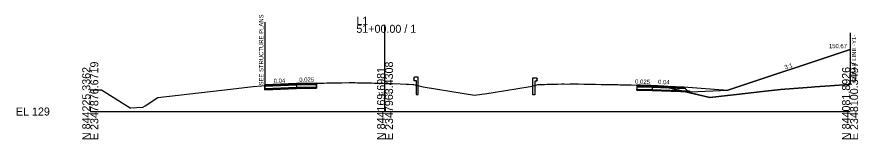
# Model space of a CAD drawing. Extents: x -26 to 2348258, y -10 to 844496.
# Drawn here: x 1322.4 to 1616.7, y 1990.3 to 2033.2 of the extents above; entities that cross this region are included whole.
import ezdxf

# ---------------------------------------------------------------- set-up
doc = ezdxf.new("R2010")
doc.units = 0
for name, color, linetype in [('Exist Cross Section Cell', 7, 'Continuous'), ('Exist XS Center Line Elevation Label', 7, 'Continuous'), ('Exist XS Ground Line', 7, 'Continuous'), ('Prop CMT Guardrail Graphics', 7, 'Continuous'), ('Prop CMT Pvmt Course 1', 7, 'Continuous'), ('Prop CMT Pvmt Course 2', 7, 'Continuous'), ('Prop CMT Pvmt Course 3', 7, 'Continuous'), ('Prop CMT Pvmt Course 4', 7, 'Continuous'), ('Prop CMT Pvmt Surface', 7, 'Continuous'), ('Prop CMT Shld Paved Course 1', 7, 'Continuous'), ('Prop CMT Shld Paved Course 2', 7, 'Continuous'), ('Prop CMT Shld Paved Course 3', 7, 'Continuous'), ('Prop CMT Shld Paved Course 4', 7, 'Continuous'), ('Prop CMT Slope Grass', 7, 'Continuous'), ('Prop CMT Subgrade Earthwork', 7, 'Continuous'), ('Prop XS Earthwork Shape', 7, 'Continuous'), ('Prop XS SE Text', 7, 'Continuous'), ('Prop XS Shear Point Element', 7, 'Continuous'), ('Prop XS Shear Point Label', 7, 'Continuous')]:
    doc.layers.add(name, color=color, linetype=linetype)

msp = doc.modelspace()

# ---------------------------------------------------------------- linework, layer by layer
at = {"layer": 'Exist Cross Section Cell'}
for p, q in [((1451.19, 2000), (1451.19, 2030.36)), ((1348.12, 2000), (1451.19, 2000)), ((1451.19, 2000), (1613.85, 2000))]:
    msp.add_line(p, q, dxfattribs=at)
at = {"layer": 'Exist XS Ground Line'}
msp.add_lwpolyline([(1348.12, 2007.6), (1352.05, 2007.55), (1361.11, 2001.83), (1362.02, 2001.27), (1362.36, 2001.28), (1366.54, 2001.49), (1367.35, 2001.97), (1371.77, 2004.91), (1394.16, 2007.46), (1405.13, 2008.81), (1410.97, 2009.27), (1411.43, 2009.29), (1414.9, 2009.54), (1415.7, 2009.56), (1416.99, 2009.63), (1417.96, 2009.67), (1419.61, 2009.73), (1420.86, 2009.77), (1421.62, 2009.79), (1423.83, 2009.86), (1426.22, 2009.92), (1426.7, 2009.93), (1427.32, 2009.93), (1428.48, 2009.95), (1429.77, 2009.98), (1430.83, 2010), (1431.99, 2010.02), (1432.73, 2010.04), (1433.81, 2010.05), (1435.71, 2010.08), (1436.08, 2010.09), (1438.68, 2010.12), (1439.38, 2010.12), (1439.87, 2010.11), (1440.73, 2010.1), (1441.62, 2010.09), (1442.8, 2010.07), (1444.69, 2010.04), (1446.44, 2009.99), (1447.55, 2009.96), (1448.26, 2009.95), (1449.35, 2009.92), (1450.55, 2009.89), (1451.41, 2009.86), (1453.97, 2009.77), (1456.47, 2009.67), (1458.55, 2009.58), (1459.07, 2009.55), (1459.4, 2009.54), (1460.88, 2009.46), (1461.33, 2009.44), (1463.11, 2009), (1464.53, 2008.66), (1478.93, 2006.29), (1482.49, 2005.7), (1486.78, 2006.36), (1489.03, 2006.7), (1502.02, 2008.7), (1503.05, 2008.96), (1504.8, 2009.42), (1505.28, 2009.43), (1506.29, 2009.48), (1507, 2009.5), (1507.96, 2009.53), (1509.38, 2009.57), (1509.98, 2009.59), (1511.58, 2009.63), (1512.93, 2009.65), (1513.83, 2009.65), (1515.07, 2009.62), (1515.87, 2009.67), (1518.85, 2009.65), (1520.69, 2009.63), (1521.86, 2009.61), (1523.45, 2009.58), (1524.26, 2009.57), (1524.8, 2009.56), (1526.76, 2009.51), (1527.25, 2009.5), (1527.74, 2009.49), (1528.1, 2009.49), (1529.69, 2009.46), (1530.75, 2009.44), (1531.52, 2009.43), (1532.7, 2009.4), (1533.29, 2009.39), (1533.7, 2009.38), (1535.12, 2009.35), (1536.69, 2009.31), (1537.29, 2009.3), (1539.09, 2009.25), (1539.84, 2009.22), (1540.57, 2009.2), (1541.91, 2009.15), (1542.81, 2009.12), (1544.31, 2009.06), (1545.6, 2009), (1546.77, 2008.95), (1548.07, 2008.88), (1548.66, 2008.84), (1551.35, 2008.07), (1551.74, 2007.96), (1553.79, 2007.48), (1564.79, 2004.9), (1572.01, 2005.68), (1574.16, 2005.99), (1583.23, 2007.05), (1589.54, 2007.72), (1598.89, 2008.44), (1600.35, 2008.58), (1601.5, 2008.64), (1606.77, 2009), (1613.38, 2009.43), (1613.85, 2009.47)], dxfattribs=at)
at = {"layer": 'Prop CMT Guardrail Graphics'}
for p, q in [((1461.46, 2011.97), (1461.19, 2011.68)), ((1461.19, 2011.68), (1461.46, 2011.39)), ((1461.46, 2011.39), (1461.19, 2011.1)), ((1461.19, 2011.1), (1461.46, 2010.81)), ((1462.79, 2011.97), (1461.46, 2011.97)), ((1461.46, 2010.81), (1462.13, 2010.81)), ((1462.13, 2010.81), (1462.13, 2005.97)), ((1462.79, 2005.97), (1462.79, 2011.97)), ((1502.91, 2005.85), (1502.91, 2011.85)), ((1502.91, 2011.85), (1504.24, 2011.85)), ((1504.24, 2010.68), (1503.57, 2010.68)), ((1503.57, 2010.68), (1503.57, 2005.85)), ((1504.24, 2011.85), (1504.51, 2011.55)), ((1504.51, 2011.55), (1504.24, 2011.26)), ((1504.24, 2011.26), (1504.51, 2010.97)), ((1504.51, 2010.97), (1504.24, 2010.68)), ((1462.13, 2005.97), (1462.79, 2005.97)), ((1503.57, 2005.85), (1502.91, 2005.85))]:
    msp.add_line(p, q, dxfattribs=at)
at = {"layer": 'Prop CMT Pvmt Course 1'}
for p, q in [((1427.19, 2009.8), (1427.19, 2009.93)), ((1427.19, 2009.68), (1427.19, 2009.93)), ((1409.19, 2009.19), (1409.19, 2009.31)), ((1409.19, 2009.06), (1409.19, 2009.31)), ((1420.19, 2009.63), (1420.19, 2009.75)), ((1420.19, 2009.5), (1420.19, 2009.75)), ((1544.59, 2008.99), (1544.59, 2009.11)), ((1544.59, 2008.86), (1544.59, 2009.11))]:
    msp.add_line(p, q, dxfattribs=at)
at = {"layer": 'Prop CMT Pvmt Course 2'}
for p, q in [((1420.19, 2009.5), (1409.19, 2009.06)), ((1409.19, 2008.73), (1409.19, 2009.06)), ((1427.19, 2009.68), (1420.19, 2009.5)), ((1420.19, 2009.17), (1420.19, 2009.5)), ((1427.19, 2009.34), (1427.19, 2009.68)), ((1539.3, 2008.99), (1544.59, 2008.86)), ((1544.59, 2008.86), (1555.89, 2008.41)), ((1544.59, 2008.52), (1544.59, 2008.86))]:
    msp.add_line(p, q, dxfattribs=at)
at = {"layer": 'Prop CMT Pvmt Course 3'}
for p, q in [((1420.19, 2009.17), (1409.19, 2008.73)), ((1409.19, 2008.73), (1409.19, 2007.94)), ((1427.19, 2009.35), (1420.19, 2009.17)), ((1420.19, 2009.17), (1420.19, 2008.38)), ((1427.19, 2009.34), (1427.19, 2008.55)), ((1539.3, 2008.66), (1544.59, 2008.53)), ((1539.3, 2008.66), (1539.3, 2007.87)), ((1544.59, 2008.53), (1556.24, 2008.06)), ((1544.59, 2008.52), (1544.59, 2007.73))]:
    msp.add_line(p, q, dxfattribs=at)
at = {"layer": 'Prop CMT Pvmt Course 4'}
for p, q in [((1420.19, 2008.38), (1409.19, 2007.94)), ((1420.19, 2008.04), (1409.19, 2007.6)), ((1409.19, 2007.61), (1409.19, 2007.94)), ((1427.19, 2008.55), (1420.19, 2008.38)), ((1420.19, 2008.05), (1420.19, 2008.38)), ((1427.19, 2008.22), (1420.19, 2008.04)), ((1427.19, 2008.22), (1427.19, 2008.55)), ((1539.3, 2007.87), (1544.59, 2007.74)), ((1539.3, 2007.53), (1539.3, 2007.87)), ((1539.3, 2007.53), (1544.59, 2007.4)), ((1544.59, 2007.73), (1557.04, 2007.26)), ((1544.59, 2007.4), (1544.59, 2007.73)), ((1544.59, 2007.4), (1557.87, 2006.91))]:
    msp.add_line(p, q, dxfattribs=at)
at = {"layer": 'Prop CMT Pvmt Surface'}
for p, q in [((1427.19, 2009.93), (1420.19, 2009.75)), ((1420.19, 2009.75), (1409.19, 2009.31)), ((1539.3, 2009.24), (1544.59, 2009.11)), ((1544.59, 2009.11), (1555.63, 2008.67))]:
    msp.add_line(p, q, dxfattribs=at)
at = {"layer": 'Prop CMT Shld Paved Course 1'}
msp.add_line((1555.63, 2008.67), (1555.89, 2008.41), dxfattribs=at)
at = {"layer": 'Prop CMT Shld Paved Course 2'}
msp.add_line((1555.89, 2008.41), (1556.23, 2008.07), dxfattribs=at)
at = {"layer": 'Prop CMT Shld Paved Course 3'}
msp.add_line((1557.04, 2007.26), (1556.23, 2008.07), dxfattribs=at)
at = {"layer": 'Prop CMT Shld Paved Course 4'}
for p, q in [((1557.04, 2007.26), (1557.54, 2007.24)), ((1557.54, 2007.24), (1557.87, 2006.91))]:
    msp.add_line(p, q, dxfattribs=at)
at = {"layer": 'Prop CMT Slope Grass'}
for p, q in [((1613.84, 2021.67), (1571.12, 2007.43)), ((1613.84, 2021.67), (1613.84, 2009.47)), ((1555.63, 2008.67), (1571.12, 2007.43))]:
    msp.add_line(p, q, dxfattribs=at)
at = {"layer": 'Prop CMT Subgrade Earthwork'}
for p, q in [((1427.19, 2009.93), (1427.19, 2008.22)), ((1427.19, 2009.93), (1427.19, 2008.22)), ((1409.19, 2007.6), (1409.19, 2009.31)), ((1420.19, 2008.04), (1409.19, 2007.6)), ((1427.19, 2008.22), (1420.19, 2008.04)), ((1539.3, 2009.24), (1539.3, 2007.53)), ((1539.3, 2009.24), (1539.3, 2007.53)), ((1544.59, 2007.4), (1557.87, 2006.91)), ((1557.87, 2006.91), (1571.12, 2007.43))]:
    msp.add_line(p, q, dxfattribs=at)
msp.add_lwpolyline([(1539.3, 2007.53), (1544.59, 2007.4)], dxfattribs=at)
at = {"layer": 'Prop XS Earthwork Shape'}
for points in [[(1613.84, 2021.67), (1613.84, 2009.47), (1613.38, 2009.43), (1606.77, 2009), (1601.5, 2008.64), (1600.35, 2008.58), (1598.89, 2008.44), (1589.54, 2007.72), (1583.23, 2007.05), (1574.16, 2005.99), (1572.01, 2005.68), (1564.79, 2004.9), (1555.9, 2006.98), (1557.87, 2006.91), (1571.12, 2007.43)], [(1427.19, 2009.93), (1420.85, 2009.77), (1419.61, 2009.73), (1419.35, 2009.72), (1416.72, 2009.61), (1415.7, 2009.56), (1414.9, 2009.54), (1411.43, 2009.29), (1410.97, 2009.27), (1409.19, 2009.13), (1409.19, 2007.6), (1420.19, 2008.04), (1427.19, 2008.22)], [(1427.19, 2009.93), (1420.85, 2009.77), (1420.86, 2009.77), (1421.62, 2009.79), (1423.83, 2009.86), (1426.22, 2009.92), (1426.7, 2009.93)], [(1419.35, 2009.72), (1416.72, 2009.61), (1416.99, 2009.63), (1417.96, 2009.67)], [(1544.59, 2007.4), (1555.9, 2006.98), (1553.79, 2007.48), (1551.74, 2007.96), (1551.35, 2008.07), (1548.66, 2008.84), (1548.07, 2008.88), (1546.77, 2008.95), (1545.6, 2009), (1544.31, 2009.06), (1542.81, 2009.12), (1541.91, 2009.15), (1540.57, 2009.2), (1539.84, 2009.22), (1539.3, 2009.24), (1539.3, 2007.53)]]:
    msp.add_lwpolyline(points, close=True, dxfattribs=at)
at = {"layer": 'Prop XS Shear Point Element'}
for p, q in [((1409.19, 2031.33), (1409.19, 2007.6)), ((1613.84, 2027.6), (1613.84, 2009.47))]:
    msp.add_line(p, q, dxfattribs=at)

# ---------------------------------------------------------------- texts
at = {"layer": 'Exist Cross Section Cell'}
for s, p in [('51+00.00 / 1', (1441.19, 2027.56)), ('L1', (1441.19, 2030.36)), ('EL 129', (1322.12, 1998.6))]:
    msp.add_text(s, height=2.8, dxfattribs=at).set_placement(p)
for s, p in [('E 2347876.6719', (1350.92, 1990)), ('E 2347963.4308', (1453.99, 1990)), ('E 2348100.3497', (1616.65, 1990)), ('N 844225.3362', (1348.12, 1990)), ('N 844169.6981', (1451.19, 1990)), ('N 844081.8926', (1613.85, 1990))]:
    msp.add_text(s, height=2.8, rotation=90, dxfattribs=at).set_placement(p)
at = {"layer": 'Exist XS Center Line Elevation Label'}
msp.add_text('138.87', height=1.2, dxfattribs=at).set_placement((1448.74, 2005.56))
at = {"layer": 'Prop XS SE Text'}
for s, rotation, p in [('3:1', 18.4349, (1591.17, 2014.71)), ('0.04', 2.2471, (1412.31, 2009.94)), ('0.025', 1.3886, (1421.23, 2010.36)), ('0.025', 358.5679, (1538.66, 2009.75)), ('0.04', 358.0849, (1546.69, 2009.63))]:
    msp.add_text(s, height=1.5, rotation=rotation, dxfattribs=at).set_placement(p)
at = {"layer": 'Prop XS Shear Point Label'}
for s, p in [('SEE STRUCTURE PLANS', (1408.64, 2009.12)), ('SHEAR LINE -Y1-', (1615.98, 2010.07))]:
    msp.add_text(s, height=1.5, rotation=90, dxfattribs=at).set_placement(p)
msp.add_text('150.67', height=1.5, dxfattribs=at).set_placement((1606.43, 2022.17))

doc.saveas('drawing.dxf')
